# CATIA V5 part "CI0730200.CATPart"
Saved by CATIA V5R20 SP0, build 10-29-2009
Part number: CI0730200
Bounding box of the stored display mesh (mm): x -29 to 29, y -25.758 to 245, z -29.41 to 34.617
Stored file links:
  C:\Users\Raffaele\Desktop\3D X SITO CF\BOLEX\19-INCLINED ASSEMBLY REF_CI\CI0730200.CATPart
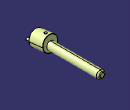
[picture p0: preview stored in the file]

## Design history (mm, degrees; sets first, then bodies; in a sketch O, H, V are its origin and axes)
Set1
  DatumSurface1 to DatumSurface16 "MANIFOLD_SOLID_BREP #397"
  DatumSurface17 to DatumSurface39 "MANIFOLD_SOLID_BREP #1146"
Body1 (main body)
